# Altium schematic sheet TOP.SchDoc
size A3
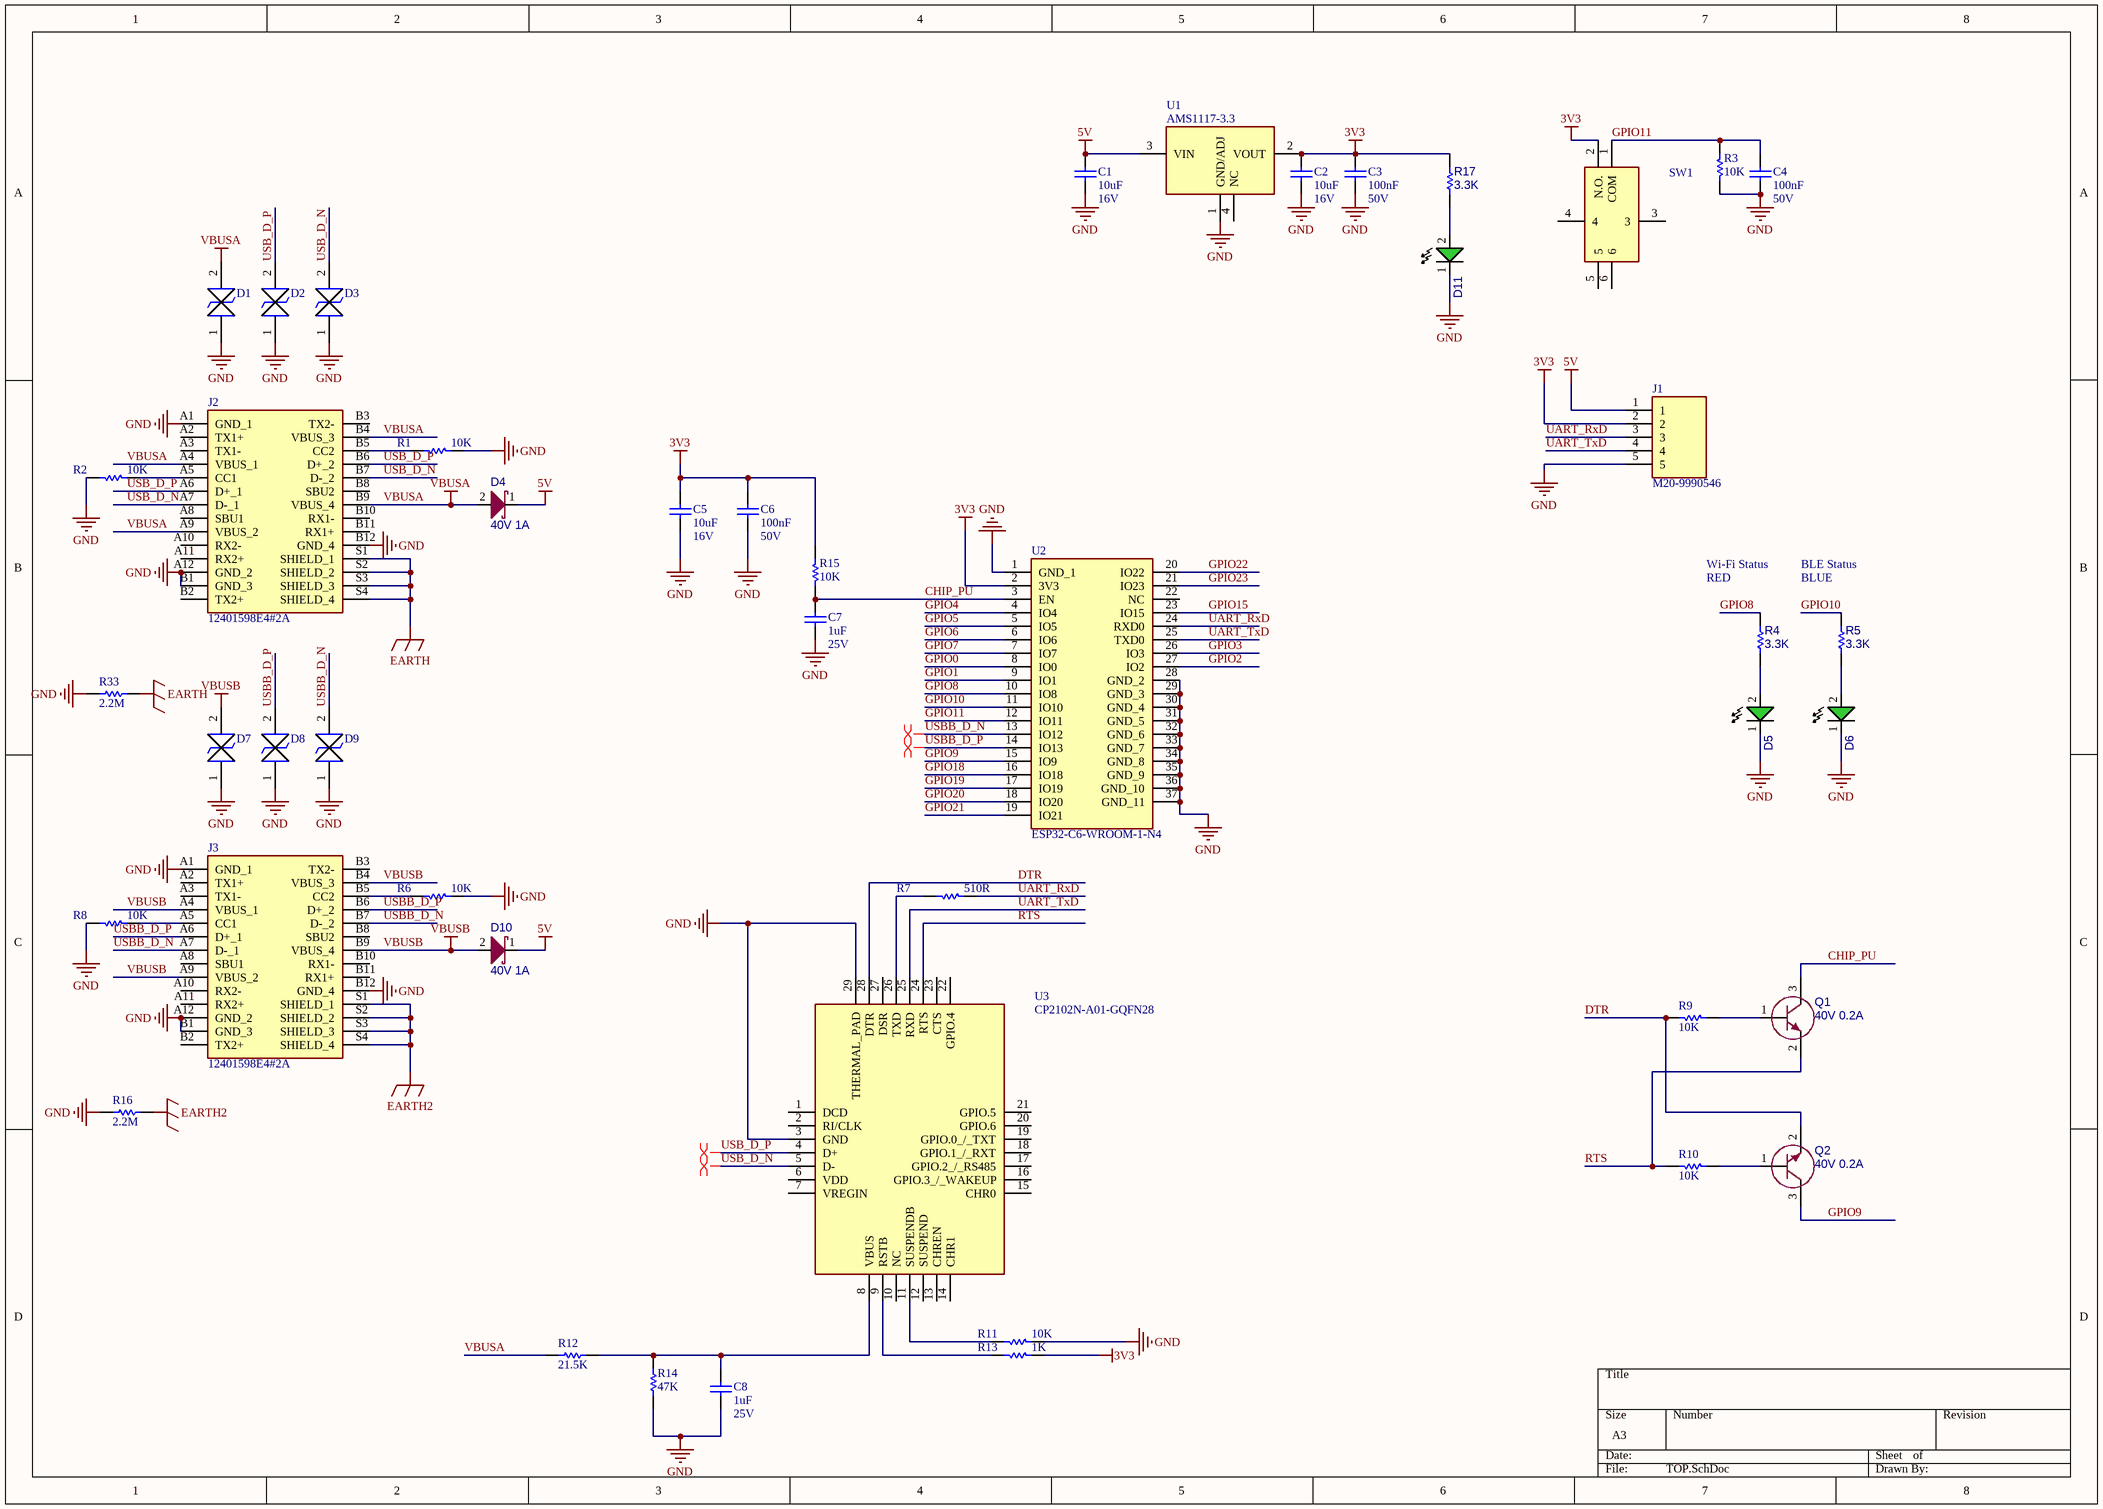
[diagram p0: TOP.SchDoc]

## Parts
C1  value 10uF  Voltage: 16V  [CAP_0805]  (hidden comment: CAP)
C2  value 10uF  Voltage: 16V  [CAP_0805]  (hidden comment: CAP)
C3  value 100nF  Voltage: 50V  [CAP_0603]  (hidden comment: CAP)
C4  value 100nF  Voltage: 50V  [CAP_0603]  (hidden comment: CAP)
C5  value 10uF  Voltage: 16V  [CAP_0805]  (hidden comment: CAP)
C6  value 100nF  Voltage: 50V  [CAP_0603]  (hidden comment: CAP)
C7  value 1uF  Voltage: 25V  [CAP_0603]  (hidden comment: CL10A105KA8NNNC)
C8  value 1uF  Voltage: 25V  [CAP_0603]  (hidden comment: CL10A105KA8NNNC)
D1  ATV02W5V0B-HF  [SODFL3718X130N]  (value not drawn)
D2  ATV02W5V0B-HF  [SODFL3718X130N]  (value not drawn)
D3  ATV02W5V0B-HF  [SODFL3718X130N]  (value not drawn)
D4  value 40V 1A  [SOD-123]  (hidden comment: PMEG4010EGWJ)
D5  PSC-1608U52GC-G4  [LED_0603_GRN]  (value not drawn)
D6  PSC-1608U52GC-G4  [LED_0603_GRN]  (value not drawn)
D7  ATV02W5V0B-HF  [SODFL3718X130N]  (value not drawn)
D8  ATV02W5V0B-HF  [SODFL3718X130N]  (value not drawn)
D9  ATV02W5V0B-HF  [SODFL3718X130N]  (value not drawn)
D10  value 40V 1A  [SOD-123]  (hidden comment: PMEG4010EGWJ)
D11  PSC-1608U52GC-G4  [LED_0603_GRN]  (value not drawn)
J1  M20-9990546  [HDRV5W64P0X254_1X5_1270X254X864P]
J2  12401598E4#2A  [12401598E42A]
J3  12401598E4#2A  [12401598E42A]
Q1  value 40V 0.2A  [SOT23]  (hidden comment: MMBT3904-7-F)
Q2  value 40V 0.2A  [SOT23]  (hidden comment: MMBT3904-7-F)
R1  value 10K  [RES_0603]  (hidden comment: RES)
R2  value 10K  [RES_0603]  (hidden comment: RES)
R3  value 10K  [RES_0603]  (hidden comment: RES)
R4  value 3.3K  [RES_0603]  (hidden comment: 0603SAF3301T5E)
R5  value 3.3K  [RES_0603]  (hidden comment: 0603SAF3301T5E)
R6  value 10K  [RES_0603]  (hidden comment: RES)
R7  value 510R  [R0603]  (hidden comment: 0603SAJ0511T5E)
R8  value 10K  [RES_0603]  (hidden comment: RES)
R9  value 10K  [RES_0603]  (hidden comment: RES)
R10  value 10K  [RES_0603]  (hidden comment: RES)
R11  value 10K  [RES_0603]  (hidden comment: RES)
R12  value 21.5K  [RES_0603]  (hidden comment: 0603SAF2152T5E)
R13  value 1K  [RES_0603]  (hidden comment: RES)
R14  value 47K  [RES_0603]  (hidden comment: RES)
R15  value 10K  [RES_0603]  (hidden comment: RES)
R16  value 2.2M  [RES_0805]  (hidden comment: RES)
R17  value 3.3K  [RES_0603]  (hidden comment: 0603SAF3301T5E)
R33  value 2.2M  [RES_0805]  (hidden comment: RES)
SW1  TS32-7-35-BK-B-260-RA-SMT-TR  [TS32735BKB160RAHSMTTR]  (value not drawn)
U1  AMS1117-3.3  [SOT229P700X180-4N]
U2  ESP32-C6-WROOM-1-N4  [ESP32C6WROOM1N4]
U3  CP2102N-A01-GQFN28  [QFN50P500X500X80-29N-D]

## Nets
3V3: C2.1 C3.1 C5.1 C6.1 J1.2 R13.2 R15.2 R17.2 SW1.2(N.O.) U1.2(VOUT) U2.2(3V3)
5V: C1.1 D4.1 D10.1 J1.1 U1.3(VIN)
EARTH: J2.S1(SHIELD_1) J2.S2(SHIELD_2) J2.S3(SHIELD_3) J2.S4(SHIELD_4) R33.2
EARTH2: J3.S1(SHIELD_1) J3.S2(SHIELD_2) J3.S3(SHIELD_3) J3.S4(SHIELD_4) R16.2
GND: C1.2 C2.2 C3.2 C4.2 C5.2 C6.2 C7.2 C8.2 D1.1 D2.1 D3.1 D5.1 D6.1 D7.1 D8.1 D9.1 D11.1 J1.5 J2.A1(GND_1) J2.A12(GND_2) J2.B1(GND_3) J2.B12(GND_4) J3.A1(GND_1) J3.A12(GND_2) J3.B1(GND_3) J3.B12(GND_4) R1.2 R2.1 R3.1 R6.2 R8.1 R11.2 R14.2 R16.1 R33.1 U1.1(GND/ADJ) U2.1(GND_1) U2.28(GND_2) U2.29(GND_3) U2.30(GND_4) U2.31(GND_5) U2.32(GND_6) U2.33(GND_7) U2.34(GND_8) U2.35(GND_9) U2.36(GND_10) U2.37(GND_11) U3.3(GND) U3.29(THERMAL_PAD)
VBUSA: D1.2 D4.2 J2.A4(VBUS_1) J2.A9(VBUS_2) J2.B4(VBUS_3) J2.B9(VBUS_4) R12.1
VBUSB: D7.2 D10.2 J3.A4(VBUS_1) J3.A9(VBUS_2) J3.B4(VBUS_3) J3.B9(VBUS_4)
CHIP_PU: C7.1 Q1.3(C) R15.1 U2.3(EN)
DTR: Q2.2(E) R9.1 U3.28(DTR)
GPIO0: U2.8(IO0)
GPIO1: U2.9(IO1)
GPIO2: U2.27(IO2)
GPIO3: U2.26(IO3)
GPIO4: U2.4(IO4)
GPIO5: U2.5(IO5)
GPIO6: U2.6(IO6)
GPIO7: U2.7(IO7)
GPIO8: R4.2 U2.10(IO8)
GPIO9: Q2.3(C) U2.15(IO9)
GPIO10: R5.2 U2.11(IO10)
GPIO11: C4.1 R3.2 SW1.1(COM) U2.12(IO11)
GPIO15: U2.23(IO15)
GPIO18: U2.16(IO18)
GPIO19: U2.17(IO19)
GPIO20: U2.18(IO20)
GPIO21: U2.19(IO21)
GPIO22: U2.20(IO22)
GPIO23: U2.21(IO23)
RTS: Q1.2(E) R10.1 U3.24(RTS)
UART_RxD: J1.3 R7.2 U2.24(RXD0)
UART_TxD: J1.4 U2.25(TXD0) U3.25(RXD)
USB_D_N: D3.2 J2.A7(D-_1) J2.B7(D-_2) U3.5(D-)
USB_D_P: D2.2 J2.A6(D+_1) J2.B6(D+_2) U3.4(D+)
USBB_D_N: D9.2 J3.A7(D-_1) J3.B7(D-_2) U2.13(IO12)
USBB_D_P: D8.2 J3.A6(D+_1) J3.B6(D+_2) U2.14(IO13)
NetC8_1: C8.1 R12.2 R14.1 U3.8(VBUS)
NetD5_2: D5.2 R4.1
NetD6_2: D6.2 R5.1
NetD11_2: D11.2 R17.1
NetJ2_A5: J2.A5(CC1) R2.2
NetJ2_B5: J2.B5(CC2) R1.1
NetJ3_A5: J3.A5(CC1) R8.2
NetJ3_B5: J3.B5(CC2) R6.1
NetQ1_1: Q1.1(B) R9.2
NetQ2_1: Q2.1(B) R10.2
NetR7_1: R7.1 U3.26(TXD)
NetR11_1: R11.1 U3.11(SUSPENDB)
NetR13_1: R13.1 U3.9(RSTB)

Not connected (* = marked no-connect by the designer): J2 A2(TX1+) A3(TX1-) A8(SBU1) A10(RX2-) A11(RX2+) B2(TX2+) B3(TX2-) B8(SBU2) B10(RX1-) B11(RX1+); J3 A2(TX1+) A3(TX1-) A8(SBU1) A10(RX2-) A11(RX2+) B2(TX2+) B3(TX2-) B8(SBU2) B10(RX1-) B11(RX1+); SW1 3 4 5 6; U1 4(NC); U2 22(NC); U3 1(DCD) 2(RI/CLK) 6(VDD) 7(VREGIN) 10(NC) 12(SUSPEND) 13(CHREN) 14(CHR1) 15(CHR0) 16(GPIO.3_/_WAKEUP) 17(GPIO.2_/_RS485) 18(GPIO.1_/_RXT) 19(GPIO.0_/_TXT) 20(GPIO.6) 21(GPIO.5) 22(GPIO.4) 23(CTS) 27(DSR)

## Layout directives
differential pair; differential pair class USBA: USB_D_N, USB_D_P
differential pair; differential pair class USBB; rule Impedance Constraint [Min = 98.00    Max = 102.0    ]: USBB_D_N, USBB_D_P

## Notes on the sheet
- Wi-Fi Status
- RED
- BLE Status
- BLUE

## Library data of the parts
C1 C2 C5 = C01758: CAP CER 10UF 16VDC %10 X5R SMD; Manufacturer: Samsung; Manufacturer Part Number: CL21A106KOQNNNE
C3 C4 C6 = C01763: CAP CER 100nF 50VDC %10 X7R SMD; Manufacturer: Samsung; Manufacturer Part Number: CL10B104KB8NNNL
C7 C8 = C01757: CAP CER 1UF 25VDC %10 X5R SMD; Manufacturer: Samsung
D1-D3 D7-D9 = ATV02W5V0B-HF: TVS Diode (Bi-directional); Manufacturer: Comchip Technology
D4 D10 = PMEG4010EGWJ: DIODE SCHOTTKY 40V 1A SOD123; Manufacturer: Nexperia USA Inc.
D5 D6 D11 = LTST-C190TGKT: LED GREEN WATER CLEAR 0603 SMD; Manufacturer: HONGLITRONIC
J1 = M20-9990546: Connector; Manufacturer: Harwin
J2 J3 = 12401598E4#2A: Connector; Manufacturer: Amphenol
Q1 Q2 = MMBT3904-7-F: TRANSISTOR NPN 40V 0.2A SOT23-3; Manufacturer: Diodes Incorporated
R1-R3 R6 R8-R11 R15 = R02995: RES 0603 10k Ohms %1 1/10W 100PPM; Manufacturer: ROYALOHM; Manufacturer Part Number: 0603SAF1002T5E
R4 R5 R17 = 0603SAF3301T5E: RES.(1608) 0603 3.3K Ohms 1% 1/10W 100PPM SMT; Manufacturer: YAGEO; Manufacturer Part Number: RC0603FR-073K74L
R7 = R03005: RES.(1608) 0603 510 Ohms 5% 1/10W-S 100PPM; Manufacturer: ROYALOHM
R12 = R03011: RES.(1608) 0603 21.5K Ohms 1% 1/10W-S 100PPM; Manufacturer: ROYALOHM
R13 = R02998: RES 0603 1K Ohms 1% 1/10W-S 100PPM; Manufacturer: ROYALOHM; Manufacturer Part Number: 0603SAF1001T5E
R14 = R03000: RES 0603 47K Ohms 1% 1/10W-S 100PPM; Manufacturer: ROYALOHM; Manufacturer Part Number: 0603SAF4702T5E
R16 R33 = R01913: RES SMD 2.2M OHM 1% 1/8W 0805; Manufacturer: Yageo; Manufacturer Part Number: RC0805FR-072M2L
SW1 = TS32-7-35-BK-B-260-RA-SMT-TR: Switch; Manufacturer: Same Sky
U1 = AMS1117-3.3: Integrated Circuit; Manufacturer: Advanced
U2 = ESP32-C6-WROOM-1-N4: Integrated Circuit; Manufacturer: Espressif Systems
U3 = CP2102N-A01-GQFN28: Integrated Circuit; Manufacturer: Silicon Labs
